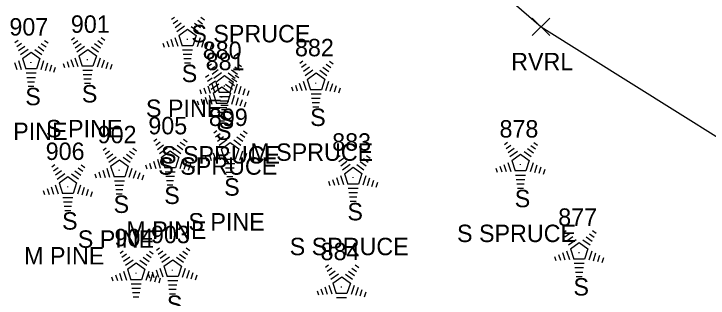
# Model space of a CAD drawing. Extents: x 1545627 to 1546562, y 571176 to 576667.
# Drawn here: x 1546131.4 to 1546211.1, y 572446 to 572478.7 of the extents above; entities that cross this region are included whole.
import ezdxf

# ---------------------------------------------------------------- set-up
doc = ezdxf.new("R2010")
doc.units = 0
for name, color, linetype in [('L_A', 7, 'Continuous'), ('L_C', 7, 'Continuous'), ('L_I', 7, 'Continuous'), ('L_TIC', 7, 'Continuous'), ('LAWE', 7, 'Continuous'), ('LTC', 7, 'Continuous')]:
    doc.layers.add(name, color=color, linetype=linetype)

msp = doc.modelspace()

# ---------------------------------------------------------------- linework, layer by layer
at = {"layer": 'L_TIC'}
for points in [[(1546190.946, 572476.2), (1546192.946, 572478.2)], [(1546192.946, 572476.2), (1546190.946, 572478.2)]]:
    msp.add_lwpolyline(points, dxfattribs=at)
at = {"layer": 'LAWE'}
msp.add_lwpolyline([(1546133.748, 572533.357), (1546159.974, 572504.858), (1546191.946, 572477.2), (1546228.308, 572454.44), (1546258.871, 572411.758), (1546265.558, 572401.332)], dxfattribs=at)
at = {"layer": 'LTC'}
for p, q in [((1546149.474, 572478.049), (1546149.829, 572478.307)), ((1546149.684, 572477.584), (1546150.213, 572477.968)), ((1546152.502, 572477.941), (1546153.051, 572477.542)), ((1546152.873, 572478.289), (1546153.292, 572477.985)), ((1546149.894, 572477.118), (1546150.597, 572477.629)), ((1546150.103, 572476.652), (1546150.982, 572477.29)), ((1546151.759, 572477.244), (1546152.569, 572476.656)), ((1546152.131, 572477.593), (1546152.81, 572477.099)), ((1546150.328, 572476.197), (1546151.339, 572476.932)), ((1546151.339, 572476.932), (1546152.337, 572476.207)), ((1546131.504, 572475.396), (1546131.859, 572475.653)), ((1546134.902, 572475.636), (1546135.322, 572475.332)), ((1546138, 572475.711), (1546138.354, 572475.968)), ((1546138.209, 572475.245), (1546138.738, 572475.63)), ((1546141.027, 572475.603), (1546141.576, 572475.204)), ((1546141.398, 572475.951), (1546141.817, 572475.647)), ((1546148.962, 572475.545), (1546149.174, 572474.893)), ((1546149.418, 572475.762), (1546149.689, 572474.926)), ((1546149.873, 572475.978), (1546150.204, 572474.959)), ((1546150.328, 572476.197), (1546150.715, 572475.004)), ((1546152.337, 572476.207), (1546151.945, 572475.004)), ((1546152.774, 572475.936), (1546152.436, 572474.896)), ((1546153.219, 572475.685), (1546152.931, 572474.801)), ((1546131.714, 572474.931), (1546132.243, 572475.315)), ((1546131.923, 572474.465), (1546132.627, 572474.976)), ((1546134.16, 572474.94), (1546134.839, 572474.446)), ((1546134.531, 572475.288), (1546135.081, 572474.889)), ((1546138.419, 572474.78), (1546139.123, 572475.291)), ((1546138.628, 572474.314), (1546139.507, 572474.952)), ((1546140.285, 572474.906), (1546141.094, 572474.317)), ((1546140.656, 572475.255), (1546141.335, 572474.761)), ((1546148.507, 572475.328), (1546148.659, 572474.86)), ((1546151.945, 572475.004), (1546150.715, 572475.004)), ((1546153.663, 572475.435), (1546153.426, 572474.706)), ((1546154.107, 572475.185), (1546153.921, 572474.611)), ((1546132.133, 572473.999), (1546133.011, 572474.637)), ((1546132.357, 572473.544), (1546133.369, 572474.278)), ((1546133.369, 572474.278), (1546134.366, 572473.553)), ((1546133.789, 572474.591), (1546134.599, 572474.003)), ((1546138.853, 572473.859), (1546139.865, 572474.593)), ((1546139.865, 572474.593), (1546140.862, 572473.868)), ((1546140.862, 572473.868), (1546140.471, 572472.665)), ((1546151.907, 572474.504), (1546150.762, 572474.504)), ((1546151.823, 572474.004), (1546150.835, 572474.004)), ((1546131.447, 572473.108), (1546131.719, 572472.273)), ((1546131.903, 572473.325), (1546132.234, 572472.306)), ((1546132.357, 572473.544), (1546132.744, 572472.351)), ((1546134.366, 572473.553), (1546133.975, 572472.351)), ((1546134.804, 572473.283), (1546134.466, 572472.243)), ((1546137.488, 572473.207), (1546137.699, 572472.555)), ((1546137.943, 572473.423), (1546138.214, 572472.588)), ((1546138.398, 572473.64), (1546138.729, 572472.62)), ((1546138.853, 572473.859), (1546139.24, 572472.665)), ((1546141.299, 572473.597), (1546140.961, 572472.558)), ((1546141.744, 572473.347), (1546141.456, 572472.462)), ((1546142.188, 572473.097), (1546141.951, 572472.367)), ((1546151.739, 572473.504), (1546150.908, 572473.504)), ((1546164.234, 572473.012), (1546164.589, 572473.269)), ((1546167.632, 572473.252), (1546168.052, 572472.948)), ((1546133.975, 572472.351), (1546132.744, 572472.351)), ((1546135.248, 572473.032), (1546134.961, 572472.148)), ((1546135.693, 572472.782), (1546135.456, 572472.053)), ((1546136.137, 572472.532), (1546135.95, 572471.958)), ((1546137.032, 572472.99), (1546137.184, 572472.522)), ((1546140.471, 572472.665), (1546139.24, 572472.665)), ((1546142.633, 572472.847), (1546142.446, 572472.272)), ((1546151.656, 572473.004), (1546150.981, 572473.004)), ((1546153.727, 572472.701), (1546154.081, 572472.958)), ((1546153.936, 572472.235), (1546154.465, 572472.619)), ((1546154.146, 572471.769), (1546154.85, 572472.281)), ((1546156.754, 572472.593), (1546157.303, 572472.194)), ((1546157.125, 572472.941), (1546157.544, 572472.636)), ((1546164.444, 572472.547), (1546164.973, 572472.931)), ((1546164.653, 572472.081), (1546165.357, 572472.592)), ((1546166.89, 572472.556), (1546167.569, 572472.062)), ((1546167.261, 572472.904), (1546167.811, 572472.505)), ((1546133.937, 572471.851), (1546132.792, 572471.851)), ((1546140.432, 572472.165), (1546139.288, 572472.165)), ((1546140.348, 572471.665), (1546139.36, 572471.665)), ((1546153.408, 572471.417), (1546153.762, 572471.674)), ((1546154.355, 572471.304), (1546155.234, 572471.941)), ((1546154.58, 572470.849), (1546155.592, 572471.583)), ((1546155.592, 572471.583), (1546156.589, 572470.858)), ((1546156.012, 572471.896), (1546156.821, 572471.307)), ((1546156.383, 572472.244), (1546157.062, 572471.751)), ((1546156.806, 572471.657), (1546157.225, 572471.353)), ((1546164.863, 572471.615), (1546165.741, 572472.253)), ((1546165.087, 572471.16), (1546166.099, 572471.894)), ((1546166.099, 572471.894), (1546167.096, 572471.169)), ((1546166.519, 572472.207), (1546167.329, 572471.619)), ((1546133.853, 572471.351), (1546132.864, 572471.351)), ((1546133.769, 572470.851), (1546132.937, 572470.851)), ((1546140.265, 572471.165), (1546139.433, 572471.165)), ((1546153.617, 572470.951), (1546154.146, 572471.336)), ((1546153.827, 572470.486), (1546154.531, 572470.997)), ((1546154.58, 572470.849), (1546154.967, 572469.655)), ((1546156.064, 572470.961), (1546156.743, 572470.467)), ((1546156.589, 572470.858), (1546156.198, 572469.655)), ((1546156.435, 572471.309), (1546156.984, 572470.91)), ((1546164.177, 572470.724), (1546164.449, 572469.889)), ((1546164.633, 572470.941), (1546164.964, 572469.922)), ((1546165.087, 572471.16), (1546165.474, 572469.967)), ((1546167.096, 572471.169), (1546166.705, 572469.967)), ((1546167.534, 572470.899), (1546167.196, 572469.859)), ((1546133.685, 572470.351), (1546133.01, 572470.351)), ((1546140.181, 572470.665), (1546139.506, 572470.665)), ((1546152.759, 572469.98), (1546152.911, 572469.512)), ((1546153.215, 572470.196), (1546153.426, 572469.545)), ((1546153.67, 572470.413), (1546153.941, 572469.578)), ((1546154.036, 572470.02), (1546154.915, 572470.658)), ((1546154.125, 572470.629), (1546154.456, 572469.61)), ((1546154.261, 572469.565), (1546155.273, 572470.299)), ((1546155.273, 572470.299), (1546156.27, 572469.574)), ((1546155.693, 572470.612), (1546156.502, 572470.023)), ((1546157.026, 572470.587), (1546156.688, 572469.548)), ((1546157.471, 572470.337), (1546157.183, 572469.452)), ((1546157.915, 572470.087), (1546157.678, 572469.357)), ((1546163.267, 572470.291), (1546163.419, 572469.823)), ((1546163.722, 572470.508), (1546163.934, 572469.856)), ((1546166.705, 572469.967), (1546165.474, 572469.967)), ((1546167.978, 572470.648), (1546167.691, 572469.764)), ((1546168.423, 572470.398), (1546168.186, 572469.669)), ((1546168.867, 572470.148), (1546168.68, 572469.574)), ((1546153.351, 572469.129), (1546153.622, 572468.294)), ((1546153.806, 572469.346), (1546154.137, 572468.326)), ((1546154.261, 572469.565), (1546154.648, 572468.371)), ((1546156.198, 572469.655), (1546154.967, 572469.655)), ((1546156.159, 572469.155), (1546155.015, 572469.155)), ((1546156.27, 572469.574), (1546155.878, 572468.371)), ((1546156.707, 572469.303), (1546156.369, 572468.264)), ((1546158.36, 572469.836), (1546158.173, 572469.262)), ((1546166.667, 572469.467), (1546165.522, 572469.467)), ((1546152.44, 572468.696), (1546152.592, 572468.228)), ((1546152.896, 572468.913), (1546153.107, 572468.261)), ((1546155.878, 572468.371), (1546154.648, 572468.371)), ((1546156.075, 572468.655), (1546155.087, 572468.655)), ((1546157.152, 572469.053), (1546156.864, 572468.168)), ((1546157.596, 572468.803), (1546157.359, 572468.073)), ((1546158.041, 572468.553), (1546157.854, 572467.978)), ((1546166.583, 572468.967), (1546165.594, 572468.967)), ((1546166.499, 572468.467), (1546165.667, 572468.467)), ((1546155.84, 572467.871), (1546154.696, 572467.871)), ((1546155.992, 572468.155), (1546155.16, 572468.155)), ((1546155.908, 572467.655), (1546155.233, 572467.655)), ((1546166.415, 572467.967), (1546165.74, 572467.967)), ((1546155.756, 572467.371), (1546154.768, 572467.371)), ((1546155.673, 572466.871), (1546154.841, 572466.871)), ((1546155.589, 572466.371), (1546154.914, 572466.371)), ((1546154.352, 572465.012), (1546154.706, 572465.269)), ((1546157.75, 572465.252), (1546158.169, 572464.948)), ((1546147.468, 572464.055), (1546147.823, 572464.313)), ((1546150.866, 572464.296), (1546151.285, 572463.991)), ((1546154.561, 572464.547), (1546155.09, 572464.931)), ((1546154.771, 572464.081), (1546155.474, 572464.592)), ((1546157.008, 572464.556), (1546157.687, 572464.062)), ((1546157.379, 572464.904), (1546157.928, 572464.505)), ((1546147.678, 572463.59), (1546148.207, 572463.974)), ((1546147.887, 572463.124), (1546148.591, 572463.635)), ((1546150.124, 572463.599), (1546150.803, 572463.105)), ((1546150.495, 572463.947), (1546151.045, 572463.548)), ((1546154.98, 572463.615), (1546155.859, 572464.253)), ((1546155.205, 572463.16), (1546156.217, 572463.894)), ((1546156.217, 572463.894), (1546157.214, 572463.169)), ((1546156.637, 572464.207), (1546157.446, 572463.619)), ((1546187.733, 572463.685), (1546188.087, 572463.942)), ((1546187.942, 572463.219), (1546188.471, 572463.604)), ((1546190.76, 572463.577), (1546191.309, 572463.178)), ((1546191.131, 572463.925), (1546191.55, 572463.621)), ((1546141.646, 572463.03), (1546142.001, 572463.287)), ((1546141.856, 572462.564), (1546142.385, 572462.948)), ((1546144.673, 572462.922), (1546145.223, 572462.523)), ((1546145.045, 572463.27), (1546145.464, 572462.966)), ((1546148.097, 572462.658), (1546148.975, 572463.296)), ((1546148.321, 572462.203), (1546149.333, 572462.938)), ((1546149.333, 572462.938), (1546150.33, 572462.213)), ((1546149.753, 572463.251), (1546150.563, 572462.662)), ((1546154.295, 572462.724), (1546154.566, 572461.889)), ((1546154.75, 572462.941), (1546155.081, 572461.922)), ((1546155.205, 572463.16), (1546155.592, 572461.967)), ((1546157.214, 572463.169), (1546156.822, 572461.967)), ((1546157.651, 572462.899), (1546157.313, 572461.859)), ((1546188.152, 572462.754), (1546188.856, 572463.265)), ((1546188.361, 572462.288), (1546189.24, 572462.926)), ((1546190.018, 572462.88), (1546190.827, 572462.292)), ((1546190.389, 572463.229), (1546191.068, 572462.735)), ((1546142.065, 572462.098), (1546142.769, 572462.61)), ((1546142.275, 572461.633), (1546143.153, 572462.271)), ((1546142.5, 572461.178), (1546143.511, 572461.912)), ((1546143.511, 572461.912), (1546144.508, 572461.187)), ((1546143.931, 572462.225), (1546144.741, 572461.636)), ((1546144.303, 572462.573), (1546144.982, 572462.08)), ((1546147.867, 572461.984), (1546148.198, 572460.965)), ((1546148.321, 572462.203), (1546148.708, 572461.01)), ((1546150.33, 572462.213), (1546149.939, 572461.01)), ((1546150.768, 572461.942), (1546150.43, 572460.902)), ((1546153.384, 572462.291), (1546153.536, 572461.823)), ((1546153.839, 572462.508), (1546154.051, 572461.856)), ((1546156.822, 572461.967), (1546155.592, 572461.967)), ((1546158.096, 572462.648), (1546157.808, 572461.764)), ((1546158.54, 572462.398), (1546158.303, 572461.669)), ((1546158.984, 572462.148), (1546158.798, 572461.574)), ((1546168.509, 572462.177), (1546168.864, 572462.435)), ((1546168.719, 572461.712), (1546169.248, 572462.096)), ((1546171.536, 572462.069), (1546172.086, 572461.67)), ((1546171.907, 572462.418), (1546172.327, 572462.113)), ((1546188.586, 572461.833), (1546189.598, 572462.567)), ((1546189.598, 572462.567), (1546190.595, 572461.842)), ((1546135.729, 572461.113), (1546136.084, 572461.371)), ((1546139.127, 572461.354), (1546139.547, 572461.049)), ((1546142.5, 572461.178), (1546142.887, 572459.984)), ((1546144.508, 572461.187), (1546144.117, 572459.984)), ((1546146.5, 572461.334), (1546146.653, 572460.867)), ((1546146.956, 572461.551), (1546147.168, 572460.899)), ((1546147.411, 572461.768), (1546147.683, 572460.932)), ((1546151.212, 572461.691), (1546150.925, 572460.807)), ((1546151.657, 572461.441), (1546151.42, 572460.712)), ((1546152.101, 572461.191), (1546151.914, 572460.617)), ((1546156.784, 572461.467), (1546155.639, 572461.467)), ((1546168.928, 572461.246), (1546169.632, 572461.757)), ((1546169.138, 572460.78), (1546170.016, 572461.418)), ((1546170.794, 572461.373), (1546171.604, 572460.784)), ((1546171.165, 572461.721), (1546171.845, 572461.227)), ((1546187.221, 572461.181), (1546187.432, 572460.529)), ((1546187.676, 572461.397), (1546187.947, 572460.562)), ((1546188.131, 572461.614), (1546188.462, 572460.594)), ((1546188.586, 572461.833), (1546188.973, 572460.639)), ((1546190.595, 572461.842), (1546190.204, 572460.639)), ((1546191.032, 572461.572), (1546190.694, 572460.532)), ((1546191.477, 572461.321), (1546191.189, 572460.437)), ((1546135.939, 572460.648), (1546136.468, 572461.032)), ((1546136.148, 572460.182), (1546136.852, 572460.693)), ((1546136.358, 572459.716), (1546137.236, 572460.354)), ((1546138.014, 572460.309), (1546138.824, 572459.72)), ((1546138.385, 572460.657), (1546139.064, 572460.163)), ((1546138.756, 572461.005), (1546139.306, 572460.606)), ((1546140.679, 572460.309), (1546140.831, 572459.841)), ((1546141.134, 572460.526), (1546141.346, 572459.874)), ((1546141.59, 572460.742), (1546141.861, 572459.907)), ((1546142.045, 572460.958), (1546142.376, 572459.939)), ((1546144.946, 572460.916), (1546144.608, 572459.877)), ((1546145.39, 572460.666), (1546145.103, 572459.781)), ((1546145.835, 572460.416), (1546145.598, 572459.686)), ((1546149.939, 572461.01), (1546148.708, 572461.01)), ((1546149.9, 572460.51), (1546148.756, 572460.51)), ((1546156.7, 572460.967), (1546155.712, 572460.967)), ((1546156.617, 572460.467), (1546155.785, 572460.467)), ((1546169.362, 572460.325), (1546170.374, 572461.06)), ((1546169.362, 572460.325), (1546169.75, 572459.132)), ((1546170.374, 572461.06), (1546171.371, 572460.335)), ((1546171.371, 572460.335), (1546170.98, 572459.132)), ((1546186.765, 572460.964), (1546186.917, 572460.496)), ((1546190.204, 572460.639), (1546188.973, 572460.639)), ((1546191.921, 572461.071), (1546191.684, 572460.342)), ((1546192.366, 572460.821), (1546192.179, 572460.247)), ((1546136.582, 572459.261), (1546137.594, 572459.996)), ((1546137.594, 572459.996), (1546138.591, 572459.271)), ((1546144.117, 572459.984), (1546142.887, 572459.984)), ((1546146.279, 572460.166), (1546146.093, 572459.591)), ((1546149.817, 572460.01), (1546148.828, 572460.01)), ((1546149.733, 572459.51), (1546148.901, 572459.51)), ((1546156.533, 572459.967), (1546155.858, 572459.967)), ((1546167.997, 572459.673), (1546168.209, 572459.021)), ((1546168.452, 572459.89), (1546168.724, 572459.054)), ((1546168.908, 572460.106), (1546169.239, 572459.087)), ((1546171.809, 572460.064), (1546171.471, 572459.024)), ((1546172.253, 572459.814), (1546171.966, 572458.929)), ((1546172.698, 572459.564), (1546172.461, 572458.834)), ((1546190.165, 572460.139), (1546189.021, 572460.139)), ((1546190.081, 572459.639), (1546189.093, 572459.639)), ((1546135.672, 572458.826), (1546135.944, 572457.99)), ((1546136.128, 572459.042), (1546136.459, 572458.023)), ((1546136.582, 572459.261), (1546136.969, 572458.068)), ((1546138.591, 572459.271), (1546138.2, 572458.068)), ((1546139.029, 572459), (1546138.691, 572457.96)), ((1546139.473, 572458.749), (1546139.186, 572457.865)), ((1546144.079, 572459.484), (1546142.934, 572459.484)), ((1546143.995, 572458.984), (1546143.007, 572458.984)), ((1546149.649, 572459.01), (1546148.974, 572459.01)), ((1546167.542, 572459.456), (1546167.694, 572458.989)), ((1546170.98, 572459.132), (1546169.75, 572459.132)), ((1546173.142, 572459.313), (1546172.955, 572458.739)), ((1546189.998, 572459.139), (1546189.166, 572459.139)), ((1546134.762, 572458.392), (1546134.914, 572457.924)), ((1546135.217, 572458.609), (1546135.429, 572457.957)), ((1546138.2, 572458.068), (1546136.969, 572458.068)), ((1546139.918, 572458.499), (1546139.681, 572457.77)), ((1546140.362, 572458.249), (1546140.175, 572457.675)), ((1546143.911, 572458.484), (1546143.08, 572458.484)), ((1546143.828, 572457.984), (1546143.153, 572457.984)), ((1546170.942, 572458.632), (1546169.797, 572458.632)), ((1546170.858, 572458.132), (1546169.87, 572458.132)), ((1546189.914, 572458.639), (1546189.239, 572458.639)), ((1546138.162, 572457.568), (1546137.017, 572457.568)), ((1546170.774, 572457.632), (1546169.942, 572457.632)), ((1546170.69, 572457.132), (1546170.015, 572457.132)), ((1546138.078, 572457.068), (1546137.089, 572457.068)), ((1546137.994, 572456.568), (1546137.162, 572456.568)), ((1546137.91, 572456.068), (1546137.235, 572456.068)), ((1546194.478, 572453.55), (1546194.832, 572453.807)), ((1546194.687, 572453.084), (1546195.216, 572453.468)), ((1546194.897, 572452.618), (1546195.601, 572453.13)), ((1546197.505, 572453.442), (1546198.054, 572453.043)), ((1546197.876, 572453.79), (1546198.295, 572453.486)), ((1546195.106, 572452.153), (1546195.985, 572452.791)), ((1546195.331, 572451.698), (1546196.343, 572452.432)), ((1546196.343, 572452.432), (1546197.34, 572451.707)), ((1546196.763, 572452.745), (1546197.572, 572452.156)), ((1546197.134, 572453.093), (1546197.813, 572452.6)), ((1546147.769, 572451.561), (1546148.123, 572451.818)), ((1546151.167, 572451.801), (1546151.586, 572451.496)), ((1546195.331, 572451.698), (1546195.718, 572450.504)), ((1546197.34, 572451.707), (1546196.949, 572450.504)), ((1546143.575, 572451.206), (1546143.93, 572451.464)), ((1546143.785, 572450.741), (1546144.314, 572451.125)), ((1546143.994, 572450.275), (1546144.698, 572450.786)), ((1546146.231, 572450.75), (1546146.91, 572450.256)), ((1546146.602, 572451.098), (1546147.152, 572450.699)), ((1546146.973, 572451.446), (1546147.392, 572451.142)), ((1546147.978, 572451.095), (1546148.507, 572451.479)), ((1546148.188, 572450.629), (1546148.892, 572451.141)), ((1546148.397, 572450.163), (1546149.276, 572450.801)), ((1546150.054, 572450.756), (1546150.863, 572450.167)), ((1546150.425, 572451.104), (1546151.104, 572450.611)), ((1546150.796, 572451.453), (1546151.345, 572451.053)), ((1546193.51, 572450.829), (1546193.662, 572450.361)), ((1546193.966, 572451.046), (1546194.177, 572450.394)), ((1546194.421, 572451.262), (1546194.692, 572450.427)), ((1546194.876, 572451.478), (1546195.207, 572450.459)), ((1546197.777, 572451.436), (1546197.439, 572450.397)), ((1546198.222, 572451.186), (1546197.934, 572450.301)), ((1546198.666, 572450.936), (1546198.429, 572450.206)), ((1546144.204, 572449.809), (1546145.082, 572450.447)), ((1546144.428, 572449.354), (1546145.44, 572450.089)), ((1546145.44, 572450.089), (1546146.437, 572449.364)), ((1546145.86, 572450.401), (1546146.669, 572449.813)), ((1546148.622, 572449.708), (1546149.634, 572450.443)), ((1546149.634, 572450.443), (1546150.631, 572449.718)), ((1546196.949, 572450.504), (1546195.718, 572450.504)), ((1546196.91, 572450.004), (1546195.766, 572450.004)), ((1546199.111, 572450.686), (1546198.924, 572450.111)), ((1546144.428, 572449.354), (1546144.815, 572448.161)), ((1546146.437, 572449.364), (1546146.046, 572448.161)), ((1546147.712, 572449.273), (1546147.983, 572448.438)), ((1546148.167, 572449.489), (1546148.498, 572448.47)), ((1546148.622, 572449.708), (1546149.009, 572448.515)), ((1546150.631, 572449.718), (1546150.239, 572448.515)), ((1546151.068, 572449.447), (1546150.73, 572448.408)), ((1546151.513, 572449.197), (1546151.225, 572448.312)), ((1546167.178, 572449.609), (1546167.533, 572449.866)), ((1546167.388, 572449.144), (1546167.917, 572449.528)), ((1546167.597, 572448.678), (1546168.301, 572449.189)), ((1546169.834, 572449.153), (1546170.513, 572448.659)), ((1546170.205, 572449.501), (1546170.755, 572449.102)), ((1546170.576, 572449.849), (1546170.995, 572449.545)), ((1546196.826, 572449.504), (1546195.838, 572449.504)), ((1546142.607, 572448.485), (1546142.76, 572448.017)), ((1546143.063, 572448.702), (1546143.275, 572448.05)), ((1546143.518, 572448.919), (1546143.79, 572448.083)), ((1546143.974, 572449.135), (1546144.305, 572448.116)), ((1546146.874, 572449.093), (1546146.537, 572448.053)), ((1546146.801, 572448.84), (1546146.953, 572448.372)), ((1546147.319, 572448.842), (1546147.032, 572447.958)), ((1546147.257, 572449.056), (1546147.468, 572448.405)), ((1546147.764, 572448.592), (1546147.527, 572447.863)), ((1546148.208, 572448.342), (1546148.021, 572447.768)), ((1546150.239, 572448.515), (1546149.009, 572448.515)), ((1546151.957, 572448.947), (1546151.72, 572448.217)), ((1546152.402, 572448.696), (1546152.215, 572448.122)), ((1546167.807, 572448.212), (1546168.685, 572448.85)), ((1546168.031, 572447.757), (1546169.043, 572448.491)), ((1546169.043, 572448.491), (1546170.04, 572447.766)), ((1546169.463, 572448.804), (1546170.273, 572448.216)), ((1546196.743, 572449.004), (1546195.911, 572449.004)), ((1546196.659, 572448.504), (1546195.984, 572448.504)), ((1546146.046, 572448.161), (1546144.815, 572448.161)), ((1546146.007, 572447.661), (1546144.863, 572447.661)), ((1546150.201, 572448.015), (1546149.057, 572448.015)), ((1546168.031, 572447.757), (1546168.418, 572446.564)), ((1546170.04, 572447.766), (1546169.649, 572446.564)), ((1546145.924, 572447.161), (1546144.935, 572447.161)), ((1546150.117, 572447.515), (1546149.129, 572447.515)), ((1546150.034, 572447.015), (1546149.202, 572447.015)), ((1546166.21, 572446.888), (1546166.363, 572446.42)), ((1546166.666, 572447.105), (1546166.878, 572446.453)), ((1546167.121, 572447.321), (1546167.393, 572446.486)), ((1546167.577, 572447.538), (1546167.908, 572446.519)), ((1546170.478, 572447.496), (1546170.14, 572446.456)), ((1546170.922, 572447.245), (1546170.635, 572446.361)), ((1546171.367, 572446.995), (1546171.13, 572446.266)), ((1546145.84, 572446.661), (1546145.008, 572446.661)), ((1546145.756, 572446.161), (1546145.081, 572446.161)), ((1546149.95, 572446.515), (1546149.275, 572446.515)), ((1546169.649, 572446.564), (1546168.418, 572446.564)), ((1546169.61, 572446.064), (1546168.466, 572446.064)), ((1546171.811, 572446.745), (1546171.624, 572446.171))]:
    msp.add_line(p, q, dxfattribs=at)

# ---------------------------------------------------------------- texts
at = {"layer": 'L_A'}
for s, p in [('RVRL', (1546188.513, 572472.2)), ('S', (1546150.665, 572470.841)), ('S', (1546132.695, 572468.188)), ('S', (1546139.19, 572468.503)), ('S', (1546154.917, 572465.492)), ('S', (1546165.425, 572465.804)), ('S', (1546154.598, 572464.209)), ('S', (1546155.542, 572457.804)), ('S', (1546148.659, 572456.847)), ('S', (1546188.923, 572456.477)), ('S', (1546142.837, 572455.822)), ('S', (1546169.7, 572454.969)), ('S', (1546136.92, 572453.905)), ('S', (1546195.668, 572446.342)), ('S', (1546148.959, 572444.352))]:
    msp.add_text(s, height=2, dxfattribs=at).set_placement(p)
at = {"layer": 'L_C'}
for s, p in [('S SPRUCE', (1546151.774, 572475.406)), ('S PINE', (1546146.555, 572466.841)), ('M PINE', (1546128.332, 572464.188)), ('S PINE', (1546135.08, 572464.503)), ('S SPRUCE', (1546148.287, 572461.492)), ('M SPRUCE', (1546158.543, 572461.804)), ('S SPRUCE', (1546147.968, 572460.209)), ('S PINE', (1546151.432, 572453.804)), ('M PINE', (1546144.296, 572452.847)), ('S SPRUCE', (1546182.293, 572452.477)), ('S PINE', (1546138.727, 572451.822)), ('S SPRUCE', (1546163.07, 572450.969)), ('M PINE', (1546132.557, 572449.905))]:
    msp.add_text(s, height=2, dxfattribs=at).set_placement(p)
at = {"layer": 'L_I'}
for s, p in [('907', (1546130.868, 572476.188)), ('901', (1546137.931, 572476.503)), ('880', (1546153.083, 572473.492)), ('882', (1546163.677, 572473.804)), ('881', (1546153.417, 572472.209)), ('899', (1546153.786, 572465.804)), ('905', (1546146.832, 572464.847)), ('878', (1546187.175, 572464.477)), ('902', (1546141.01, 572463.822)), ('883', (1546167.952, 572462.969)), ('906', (1546135.038, 572461.905)), ('877', (1546193.92, 572454.342)), ('904', (1546142.939, 572451.998)), ('903', (1546147.133, 572452.352)), ('884', (1546166.621, 572450.401))]:
    msp.add_text(s, height=2, dxfattribs=at).set_placement(p)
at = {"layer": 'LTC'}
for p in [(1546151.222, 572475.945), (1546133.252, 572473.292), (1546139.747, 572473.607), (1546165.982, 572470.908), (1546155.474, 572470.596), (1546155.155, 572469.313), (1546156.099, 572462.908), (1546149.215, 572461.951), (1546189.48, 572461.581), (1546143.394, 572460.926), (1546170.257, 572460.073), (1546137.477, 572459.009), (1546196.225, 572451.446), (1546149.516, 572449.456), (1546145.322, 572449.102), (1546168.925, 572447.505)]:
    msp.add_text('.', height=1.037, rotation=270, dxfattribs=at).set_placement(p)

doc.saveas('drawing.dxf')
